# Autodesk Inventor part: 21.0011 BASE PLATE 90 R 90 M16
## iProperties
Created: 2009-01
Part Number: 21.0011 BASE PLATE 90 R 90 M16
Document SubType Name: Modeling
Designer: Administrator
Density: 1 g/cm^3
Author: Administrator
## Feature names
1. Base1
2. Extrusion1
